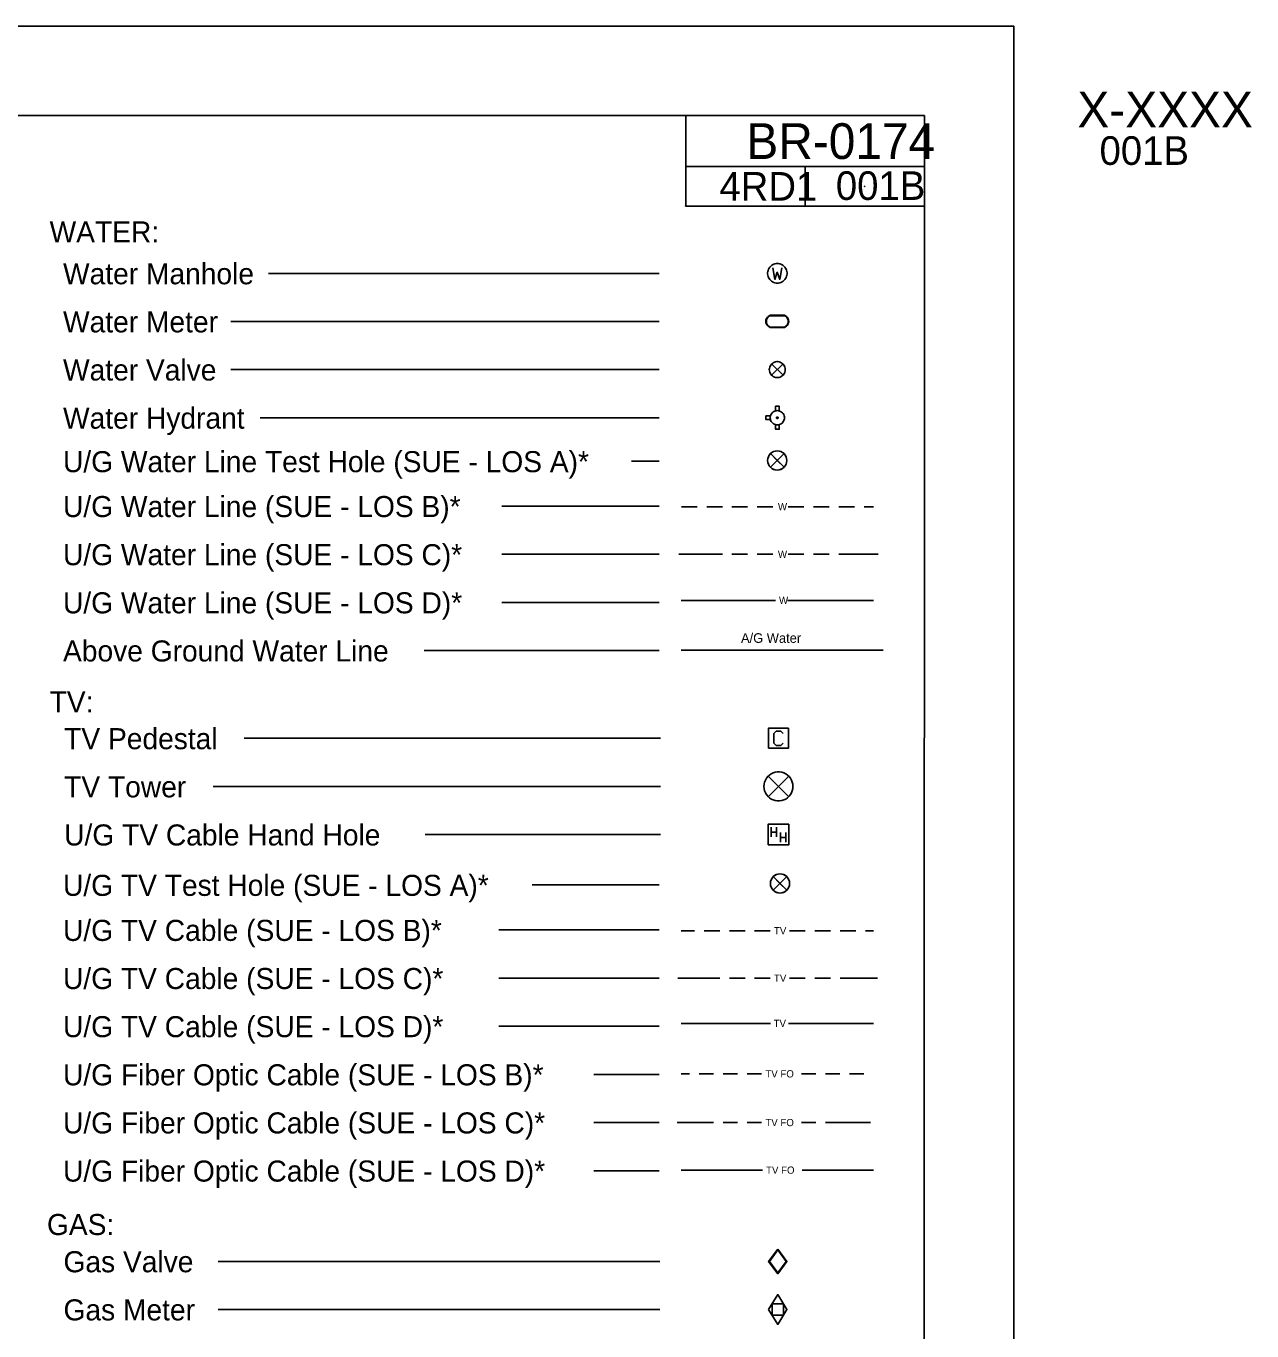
# Model space of a CAD drawing. Extents: x 1855058 to 1858918, y 1540202 to 1542502.
# Drawn here: x 1858405 to 1858918, y 1541955 to 1542502 of the extents above; entities that cross this region are included whole.
import ezdxf

# ---------------------------------------------------------------- set-up
doc = ezdxf.new("R2010")
doc.units = 0
for name, color, linetype in [('Default', 7, 'Continuous'), ('Exist Contamination Potential Cell', 7, 'Continuous'), ('Exist Right of Way Easement Marker CELL', 7, 'Continuous'), ('Prop ROW Permanent Easement CELL', 7, 'Continuous'), ('Prop WCC CELL', 7, 'Continuous'), ('Sheet Data Field CELL', 7, 'Continuous'), ('Sheet Symbology CELL', 7, 'Continuous')]:
    doc.layers.add(name, color=color, linetype=linetype)

msp = doc.modelspace()

# ---------------------------------------------------------------- linework, layer by layer
at = {"layer": 'Default'}
msp.add_lwpolyline([(1857118.6, 1542501.77), (1857118.6, 1541401.77), (1858818.6, 1541401.77), (1858818.6, 1542501.77)], close=True, dxfattribs=at)
at = {"layer": 'Exist Contamination Potential Cell'}
for p, q in [((1858818.6, 1542501.77), (1857118.6, 1542501.77)), ((1858818.6, 1541401.77), (1858818.6, 1542501.77))]:
    msp.add_line(p, q, dxfattribs=at)
for centre in [(1858731.1, 1542453.56), (1858706.1, 1542434.6), (1858756.1, 1542434.6)]:
    msp.add_circle(centre, 0.06, dxfattribs=at)
at = {"layer": 'Prop ROW Permanent Easement CELL'}
for points in [[(1858722.3, 1542322.55), (1858716.59, 1542316.84), (1858719.45, 1542319.69), (1858716.59, 1542322.55), (1858722.3, 1542316.84)], [(1858716.59, 1542322.55), (1858719.45, 1542319.69), (1858722.3, 1542322.55)], [(1858722.3, 1542316.84), (1858719.45, 1542319.69), (1858716.59, 1542316.84)]]:
    msp.add_lwpolyline(points, dxfattribs=at)
msp.add_circle((1858719.45, 1542319.69), 4.03, dxfattribs=at)
for start, end in [(45, 135), (225, 315)]:
    msp.add_arc((1858719.45, 1542319.69), 4.03, start, end, dxfattribs=at)
at = {"layer": 'Prop WCC CELL'}
for points in [[(1858723.45, 1542145.23), (1858717.75, 1542139.52), (1858720.6, 1542142.37), (1858717.75, 1542145.23), (1858723.45, 1542139.52)], [(1858717.75, 1542145.23), (1858720.6, 1542142.37), (1858723.45, 1542145.23)], [(1858723.45, 1542139.52), (1858720.6, 1542142.37), (1858717.75, 1542139.52)]]:
    msp.add_lwpolyline(points, dxfattribs=at)
msp.add_circle((1858720.6, 1542142.37), 4.03, dxfattribs=at)
for start, end in [(45, 135), (225, 315)]:
    msp.add_arc((1858720.6, 1542142.37), 4.03, start, end, dxfattribs=at)
at = {"layer": 'Sheet Data Field CELL'}
for p, q in [((1858670.03, 1542398.12), (1858506.19, 1542398.12)), ((1858670.03, 1542377.94), (1858490.4, 1542377.94)), ((1858716.4, 1542380.54), (1858722.6, 1542380.54)), ((1858716.4, 1542380.33), (1858722.6, 1542380.33)), ((1858722.56, 1542375.59), (1858716.4, 1542375.59)), ((1858722.56, 1542375.39), (1858716.4, 1542375.39)), ((1858670.03, 1542357.77), (1858490.4, 1542357.77)), ((1858670.03, 1542337.59), (1858502.76, 1542337.59)), ((1858670.03, 1542319.34), (1858658.38, 1542319.34)), ((1858670.03, 1542300.53), (1858604.07, 1542300.53)), ((1858679.29, 1542300.31), (1858685.85, 1542300.31)), ((1858689.88, 1542300.31), (1858696.44, 1542300.31)), ((1858700.48, 1542300.31), (1858707.03, 1542300.31)), ((1858711.07, 1542300.31), (1858717.63, 1542300.31)), ((1858724.09, 1542300.31), (1858730.64, 1542300.31)), ((1858734.68, 1542300.31), (1858741.24, 1542300.31)), ((1858745.27, 1542300.31), (1858751.83, 1542300.31)), ((1858755.87, 1542300.31), (1858759.84, 1542300.31)), ((1858670.03, 1542280.35), (1858604.07, 1542280.35)), ((1858678.15, 1542280.35), (1858696.44, 1542280.35)), ((1858700.48, 1542280.35), (1858707.03, 1542280.35)), ((1858711.07, 1542280.35), (1858717.63, 1542280.35)), ((1858724.09, 1542280.35), (1858730.64, 1542280.35)), ((1858734.68, 1542280.35), (1858741.24, 1542280.35)), ((1858745.27, 1542280.35), (1858761.73, 1542280.35)), ((1858670.03, 1542260.17), (1858604.07, 1542260.17)), ((1858679.12, 1542261.05), (1858718.78, 1542261.05)), ((1858723.82, 1542261.05), (1858759.84, 1542261.05)), ((1858670.03, 1542239.99), (1858571.45, 1542239.99)), ((1858679.12, 1542240.21), (1858763.89, 1542240.21)), ((1858670.51, 1542203.22), (1858496.05, 1542203.22)), ((1858719.33, 1542200.25), (1858720.63, 1542200.25)), ((1858670.51, 1542183.04), (1858483.01, 1542183.04)), ((1858716.87, 1542165.91), (1858716.87, 1542161.85)), ((1858719.19, 1542165.91), (1858719.19, 1542161.85)), ((1858670.51, 1542162.86), (1858571.93, 1542162.86)), ((1858716.87, 1542163.84), (1858719.19, 1542163.84)), ((1858720.75, 1542163.7), (1858720.75, 1542159.64)), ((1858720.75, 1542161.63), (1858723.08, 1542161.63)), ((1858723.08, 1542163.7), (1858723.08, 1542159.64)), ((1858670.03, 1542141.74), (1858616.7, 1542141.74)), ((1858670.03, 1542122.86), (1858602.75, 1542122.86)), ((1858679.12, 1542122.53), (1858684.75, 1542122.53)), ((1858688.78, 1542122.53), (1858695.34, 1542122.53)), ((1858699.38, 1542122.53), (1858705.94, 1542122.53)), ((1858709.97, 1542122.53), (1858716.53, 1542122.53)), ((1858724.6, 1542122.53), (1858731.16, 1542122.53)), ((1858735.2, 1542122.53), (1858741.75, 1542122.53)), ((1858745.79, 1542122.53), (1858752.35, 1542122.53)), ((1858756.38, 1542122.53), (1858759.84, 1542122.53)), ((1858670.03, 1542102.68), (1858602.75, 1542102.68)), ((1858677.73, 1542102.68), (1858695.34, 1542102.68)), ((1858699.38, 1542102.68), (1858705.94, 1542102.68)), ((1858709.97, 1542102.68), (1858716.53, 1542102.68)), ((1858724.6, 1542102.68), (1858731.16, 1542102.68)), ((1858735.2, 1542102.68), (1858741.75, 1542102.68)), ((1858745.79, 1542102.68), (1858761.54, 1542102.68)), ((1858670.03, 1542082.5), (1858602.75, 1542082.5)), ((1858679.12, 1542083.72), (1858716.63, 1542083.72)), ((1858724.2, 1542083.72), (1858759.84, 1542083.72)), ((1858670.03, 1542062.32), (1858642.55, 1542062.32)), ((1858679.12, 1542062.57), (1858682.66, 1542062.57)), ((1858686.69, 1542062.57), (1858692.75, 1542062.57)), ((1858696.78, 1542062.57), (1858702.83, 1542062.57)), ((1858706.87, 1542062.57), (1858712.92, 1542062.57)), ((1858729.57, 1542062.57), (1858735.62, 1542062.57)), ((1858739.66, 1542062.57), (1858745.71, 1542062.57)), ((1858749.75, 1542062.57), (1858755.8, 1542062.57)), ((1858670.03, 1542042.14), (1858642.55, 1542042.14)), ((1858677.47, 1542042.14), (1858692.75, 1542042.14)), ((1858696.78, 1542042.14), (1858702.83, 1542042.14)), ((1858706.87, 1542042.14), (1858712.92, 1542042.14)), ((1858729.57, 1542042.14), (1858735.62, 1542042.14)), ((1858739.66, 1542042.14), (1858758.56, 1542042.14)), ((1858670.03, 1542021.96), (1858642.55, 1542021.96)), ((1858679.12, 1542022.2), (1858713.21, 1542022.2)), ((1858729.86, 1542022.2), (1858759.84, 1542022.2)), ((1858670.24, 1541983.96), (1858485.11, 1541983.96)), ((1858719.69, 1541988.72), (1858716.14, 1541983.96)), ((1858716.14, 1541983.96), (1858719.69, 1541979.2)), ((1858723.23, 1541983.96), (1858719.69, 1541988.72)), ((1858719.69, 1541979.2), (1858723.23, 1541983.96)), ((1858670.24, 1541963.78), (1858485.11, 1541963.78))]:
    msp.add_line(p, q, dxfattribs=at)
for points in [[(1858719.48, 1542402.22), (1858718.96, 1542402.19), (1858718.47, 1542402.09), (1858717.97, 1542401.92), (1858717.52, 1542401.69), (1858717.09, 1542401.43), (1858716.7, 1542401.1), (1858716.34, 1542400.71), (1858716.04, 1542400.32), (1858715.78, 1542399.86), (1858715.61, 1542399.37), (1858715.48, 1542398.88), (1858715.42, 1542398.38), (1858715.42, 1542397.86), (1858715.48, 1542397.37), (1858715.61, 1542396.85), (1858715.78, 1542396.39), (1858716.04, 1542395.93), (1858716.34, 1542395.53), (1858716.7, 1542395.14), (1858717.09, 1542394.81), (1858717.52, 1542394.55), (1858717.97, 1542394.32), (1858718.47, 1542394.16), (1858718.99, 1542394.06), (1858719.48, 1542394.03), (1858720.01, 1542394.06), (1858720.5, 1542394.16), (1858720.99, 1542394.32), (1858721.45, 1542394.55), (1858721.87, 1542394.81), (1858722.27, 1542395.14), (1858722.63, 1542395.53), (1858722.92, 1542395.93), (1858723.19, 1542396.39), (1858723.35, 1542396.88), (1858723.48, 1542397.37), (1858723.55, 1542397.86), (1858723.55, 1542398.38), (1858723.48, 1542398.88), (1858723.35, 1542399.4), (1858723.19, 1542399.86), (1858722.92, 1542400.32), (1858722.63, 1542400.71), (1858722.27, 1542401.1), (1858721.87, 1542401.43), (1858721.45, 1542401.69), (1858720.99, 1542401.92), (1858720.5, 1542402.09), (1858719.97, 1542402.19), (1858719.48, 1542402.22)], [(1858717.65, 1542400.38), (1858718.5, 1542395.6), (1858719.48, 1542398.61), (1858720.5, 1542395.6), (1858721.35, 1542400.38)], [(1858716.4, 1542380.54), (1858716, 1542380.33), (1858715.63, 1542380.05), (1858715.31, 1542379.69), (1858715.07, 1542379.32), (1858714.86, 1542378.88), (1858714.74, 1542378.43), (1858714.7, 1542377.98), (1858714.74, 1542377.5), (1858714.86, 1542377.05), (1858715.07, 1542376.65), (1858715.31, 1542376.24), (1858715.63, 1542375.92), (1858716, 1542375.63), (1858716.4, 1542375.39)], [(1858716.48, 1542380.37), (1858716.08, 1542380.13), (1858715.71, 1542379.85), (1858715.39, 1542379.48), (1858715.15, 1542379.12), (1858714.98, 1542378.67), (1858714.9, 1542378.19), (1858714.9, 1542377.74), (1858714.98, 1542377.3), (1858715.15, 1542376.85), (1858715.39, 1542376.44), (1858715.71, 1542376.08), (1858716.08, 1542375.8), (1858716.48, 1542375.59)], [(1858722.48, 1542380.37), (1858722.93, 1542380.17), (1858723.29, 1542379.85), (1858723.57, 1542379.52), (1858723.82, 1542379.12), (1858723.98, 1542378.67), (1858724.06, 1542378.19), (1858724.06, 1542377.74), (1858723.98, 1542377.26), (1858723.82, 1542376.85), (1858723.57, 1542376.44), (1858723.25, 1542376.08), (1858722.89, 1542375.8), (1858722.48, 1542375.55)], [(1858722.56, 1542380.54), (1858722.97, 1542380.33), (1858723.33, 1542380.05), (1858723.66, 1542379.69), (1858723.9, 1542379.32), (1858724.1, 1542378.88), (1858724.22, 1542378.43), (1858724.26, 1542377.98), (1858724.22, 1542377.5), (1858724.1, 1542377.05), (1858723.9, 1542376.65), (1858723.66, 1542376.24), (1858723.33, 1542375.92), (1858722.97, 1542375.63), (1858722.56, 1542375.39)], [(1858722.83, 1542357.77), (1858722.8, 1542358.25), (1858722.68, 1542358.77), (1858722.5, 1542359.22), (1858722.24, 1542359.66), (1858721.94, 1542360.04), (1858721.57, 1542360.37), (1858721.16, 1542360.67), (1858720.71, 1542360.89), (1858720.23, 1542361.04), (1858719.74, 1542361.12), (1858719.22, 1542361.12), (1858718.74, 1542361.04), (1858718.25, 1542360.89), (1858717.81, 1542360.67), (1858717.4, 1542360.37), (1858717.02, 1542360.04), (1858716.73, 1542359.66), (1858716.47, 1542359.22), (1858716.28, 1542358.77), (1858716.17, 1542358.25), (1858716.13, 1542357.77), (1858716.17, 1542357.28), (1858716.28, 1542356.76), (1858716.47, 1542356.31), (1858716.73, 1542355.87), (1858717.02, 1542355.49), (1858717.4, 1542355.16), (1858717.81, 1542354.86), (1858718.25, 1542354.64), (1858718.74, 1542354.49), (1858719.22, 1542354.41), (1858719.74, 1542354.41), (1858720.23, 1542354.49), (1858720.71, 1542354.64), (1858721.16, 1542354.86), (1858721.57, 1542355.16), (1858721.94, 1542355.49), (1858722.24, 1542355.87), (1858722.5, 1542356.31), (1858722.68, 1542356.76), (1858722.8, 1542357.28), (1858722.83, 1542357.77)], [(1858721.87, 1542355.38), (1858717.1, 1542360.15), (1858719.48, 1542357.77), (1858717.1, 1542355.38), (1858721.87, 1542360.15)], [(1858719.44, 1542340.57), (1858718.98, 1542340.53), (1858718.51, 1542340.41), (1858718.05, 1542340.22), (1858717.66, 1542339.95), (1858717.31, 1542339.64), (1858717, 1542339.25), (1858716.77, 1542338.83), (1858716.62, 1542338.36), (1858716.5, 1542337.9), (1858716.5, 1542337.43), (1858716.58, 1542336.97), (1858716.69, 1542336.5), (1858716.93, 1542336.08), (1858717.2, 1542335.69), (1858717.54, 1542335.34), (1858717.93, 1542335.03), (1858718.36, 1542334.84), (1858718.82, 1542334.68), (1858719.29, 1542334.6), (1858719.75, 1542334.6), (1858720.22, 1542334.68), (1858720.68, 1542334.87), (1858721.11, 1542335.07), (1858721.5, 1542335.38), (1858721.81, 1542335.73), (1858722.08, 1542336.11), (1858722.27, 1542336.58), (1858722.43, 1542337.04), (1858722.46, 1542337.51), (1858722.43, 1542337.97), (1858722.35, 1542338.44), (1858722.15, 1542338.9), (1858721.92, 1542339.33), (1858721.61, 1542339.68), (1858721.23, 1542339.99), (1858720.84, 1542340.26), (1858720.37, 1542340.41), (1858719.91, 1542340.53), (1858719.44, 1542340.57)], [(1858718.75, 1542340.49), (1858718.75, 1542342.43), (1858720.29, 1542342.43), (1858720.29, 1542340.45)], [(1858716.62, 1542338.36), (1858714.68, 1542338.36), (1858714.68, 1542336.81), (1858716.62, 1542336.81)], [(1858718.75, 1542334.68), (1858718.75, 1542332.75), (1858720.29, 1542332.75), (1858720.29, 1542334.72)], [(1858719.48, 1542337.93), (1858719.33, 1542337.9), (1858719.21, 1542337.78), (1858719.13, 1542337.62), (1858719.17, 1542337.47), (1858719.25, 1542337.31), (1858719.4, 1542337.24), (1858719.56, 1542337.24), (1858719.71, 1542337.31), (1858719.79, 1542337.47), (1858719.83, 1542337.62), (1858719.75, 1542337.78), (1858719.64, 1542337.9), (1858719.48, 1542337.93)], [(1858715.76, 1542199.02), (1858724.17, 1542199.02), (1858724.17, 1542207.42), (1858715.76, 1542207.42), (1858715.76, 1542199.02)], [(1858721.93, 1542201.18), (1858720.93, 1542200.25), (1858719, 1542200.25), (1858718.06, 1542201.18), (1858718.06, 1542205.26), (1858719, 1542206.19), (1858720.93, 1542206.19), (1858721.93, 1542205.26)], [(1858726.04, 1542183.04), (1858725.97, 1542183.92), (1858725.77, 1542184.86), (1858725.43, 1542185.67), (1858724.96, 1542186.49), (1858724.42, 1542187.16), (1858723.75, 1542187.77), (1858723, 1542188.31), (1858722.19, 1542188.71), (1858721.31, 1542188.99), (1858720.44, 1542189.12), (1858719.49, 1542189.12), (1858718.61, 1542188.99), (1858717.74, 1542188.71), (1858716.92, 1542188.31), (1858716.18, 1542187.77), (1858715.51, 1542187.16), (1858714.97, 1542186.49), (1858714.5, 1542185.67), (1858714.16, 1542184.86), (1858713.96, 1542183.92), (1858713.89, 1542183.04), (1858713.96, 1542182.16), (1858714.16, 1542181.22), (1858714.5, 1542180.41), (1858714.97, 1542179.6), (1858715.51, 1542178.92), (1858716.18, 1542178.31), (1858716.92, 1542177.77), (1858717.74, 1542177.37), (1858718.61, 1542177.1), (1858719.49, 1542176.96), (1858720.44, 1542176.96), (1858721.31, 1542177.1), (1858722.19, 1542177.37), (1858723, 1542177.77), (1858723.75, 1542178.31), (1858724.42, 1542178.92), (1858724.96, 1542179.6), (1858725.43, 1542180.41), (1858725.77, 1542181.22), (1858725.97, 1542182.16), (1858726.04, 1542183.04)], [(1858724.29, 1542178.72), (1858715.64, 1542187.36), (1858719.96, 1542183.04), (1858715.64, 1542178.72), (1858724.29, 1542187.36)], [(1858715.62, 1542158.52), (1858724.31, 1542158.52), (1858724.31, 1542167.21), (1858715.62, 1542167.21), (1858715.62, 1542158.52)], [(1858719.69, 1541989.13), (1858715.84, 1541983.96), (1858719.69, 1541978.79), (1858723.54, 1541983.96), (1858719.69, 1541989.13)], [(1858715.84, 1541963.78), (1858719.69, 1541970.01), (1858723.54, 1541963.78), (1858719.69, 1541957.55), (1858715.84, 1541963.78)], [(1858717.31, 1541966.11), (1858722.07, 1541966.11), (1858722.07, 1541961.4), (1858717.31, 1541961.4), (1858717.31, 1541966.11)]]:
    msp.add_lwpolyline(points, dxfattribs=at)
at = {"layer": 'Sheet Symbology CELL'}
for p, q in [((1858781.1, 1542464.27), (1857156.1, 1542464.27)), ((1858681.1, 1542426.35), (1858681.1, 1542464.27)), ((1858781.08, 1541439.27), (1858781.1, 1542464.27)), ((1858781.1, 1542442.85), (1858681.1, 1542442.85)), ((1858731.1, 1542426.35), (1858731.1, 1542442.85)), ((1858781.1, 1542426.35), (1858681.1, 1542426.35))]:
    msp.add_line(p, q, dxfattribs=at)
msp.add_circle((1858681.1, 1542426.35), 0.06, dxfattribs=at)

# ---------------------------------------------------------------- texts
at = {"layer": 'Default'}
for s, height, p in [('BR-0174', 15, (1858706.5, 1542446.06)), ('4RD1', 12, (1858695.22, 1542428.6)), ('001B', 12, (1858744.02, 1542428.89))]:
    msp.add_text(s, height=height, dxfattribs=at).set_placement(p)
at = {"layer": 'Exist Right of Way Easement Marker CELL'}
for s, height, p in [('X-XXXX', 15, (1858845.23, 1542459.28)), ('001B', 12, (1858854.53, 1542443.58))]:
    msp.add_text(s, height=height, dxfattribs=at).set_placement(p)
at = {"layer": 'Sheet Data Field CELL'}
for s, height, p in [('WATER:', 8.828, (1858414.5, 1542411.08)), ('Water Manhole', 8.8282, (1858420.12, 1542393.54)), ('Water Meter', 8.8282, (1858420.12, 1542373.37)), ('Water Valve', 8.8282, (1858420.12, 1542353.19)), ('Water Hydrant', 8.8282, (1858420.12, 1542333.01)), ('U/G Water Line Test Hole (SUE - LOS A)*', 8.8282, (1858420.12, 1542314.76)), ('U/G Water Line (SUE - LOS B)*', 8.8282, (1858420.12, 1542295.95)), ('W', 3.03, (1858719.75, 1542298.79)), ('U/G Water Line (SUE - LOS C)*', 8.8282, (1858420.12, 1542275.77)), ('W', 3.03, (1858719.75, 1542278.83)), ('U/G Water Line (SUE - LOS D)*', 8.8282, (1858420.12, 1542255.59)), ('W', 3.03, (1858720.19, 1542259.54)), ('A/G Water', 4.036, (1858704.27, 1542243.23)), ('Above Ground Water Line', 8.8282, (1858420.12, 1542235.41)), ('TV:', 8.828, (1858414.5, 1542214.06)), ('TV Pedestal', 8.8282, (1858420.6, 1542198.64)), ('TV Tower', 8.828, (1858420.6, 1542178.46)), ('U/G TV Cable Hand Hole', 8.8282, (1858420.6, 1542158.28)), ('U/G TV Test Hole (SUE - LOS A)*', 8.8282, (1858420.12, 1542137.16)), ('U/G TV Cable (SUE - LOS B)*', 8.8282, (1858420.12, 1542118.28)), ('TV', 3.027, (1858718.09, 1542121.02)), ('U/G TV Cable (SUE - LOS C)*', 8.8282, (1858420.12, 1542098.1)), ('TV', 3.027, (1858718.09, 1542101.17)), ('U/G TV Cable (SUE - LOS D)*', 8.8282, (1858420.12, 1542077.92)), ('TV', 3.027, (1858717.94, 1542082.21)), ('U/G Fiber Optic Cable (SUE - LOS B)*', 8.8282, (1858420.12, 1542057.74)), ('TV FO', 3.027, (1858714.49, 1542061.05)), ('U/G Fiber Optic Cable (SUE - LOS C)*', 8.8282, (1858420.12, 1542037.57)), ('TV FO', 3.027, (1858714.49, 1542040.63)), ('U/G Fiber Optic Cable (SUE - LOS D)*', 8.8282, (1858420.12, 1542017.39)), ('TV FO', 3.027, (1858714.78, 1542020.69)), ('GAS:', 8.828, (1858413.39, 1541994.98)), ('Gas Valve', 8.828, (1858420.32, 1541979.38)), ('Gas Meter', 8.828, (1858420.32, 1541959.2))]:
    msp.add_text(s, height=height, dxfattribs=at).set_placement(p)

doc.saveas('drawing.dxf')
